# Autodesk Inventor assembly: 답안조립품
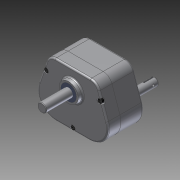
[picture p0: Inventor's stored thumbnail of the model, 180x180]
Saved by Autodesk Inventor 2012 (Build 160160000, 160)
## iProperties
Created: 2014-12
Part Number: 답안조립품
Document SubType Name: Assembly
Designer: Owner
Author: Owner
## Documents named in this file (14)
- C:\Documents and Settings\Owner\바탕 화면\441208V1002\답안조립품.iam
- C:\Documents and Settings\Owner\바탕 화면\441208V1002\1 본체.ipt
- C:\Documents and Settings\Owner\바탕 화면\441208V1002\커버.ipt
- C:\Documents and Settings\Owner\바탕 화면\441208V1002\M 5 x 35.ipt
- C:\Documents and Settings\Owner\바탕 화면\441208V1002\오일시일-D-15.ipt
- C:\Documents and Settings\Owner\바탕 화면\441208V1002\서브축.ipt
- C:\Documents and Settings\Owner\바탕 화면\441208V1002\베어링- 6203.ipt
- C:\Documents and Settings\Owner\바탕 화면\441208V1002\키5x5.ipt
- C:\Documents and Settings\Owner\바탕 화면\441208V1002\서브기어.ipt
- C:\Documents and Settings\Owner\바탕 화면\441208V1002\오일시일-D-17.ipt
- C:\Documents and Settings\Owner\바탕 화면\441208V1002\메인축.ipt
- C:\Documents and Settings\Owner\바탕 화면\441208V1002\메인기어.ipt
- C:\Documents and Settings\Owner\바탕 화면\441208V1002\멈춤링.ipt
- C:\Documents and Settings\Owner\바탕 화면\441208V1002\베어링- 6202.ipt
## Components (16 placed, 7 different names)
1. 1 본체:1
2. KS B 1003 - 미터 M 5 x 35:1 — 각도:1
3. KS B 1003 - 미터 M 5 x 35:2 — 각도:2
4. KS B 1003 - 미터 M 5 x 35:3 — 각도:3
5. KS B 2804 D D - 15 30 7:1
6. KS B 2804 D D - 15 30 7:2
7. KS B 2023 6203 - 17 x 40 x 12:1
8. KS B 2023 6203 - 17 x 40 x 12:2
9. KS B 2804 D D - 17 30 8:1
10. KS B 2023 6203 - 17 x 40 x 12:3
11. KS B 2023 6203 - 17 x 40 x 12:4
12. KS B 1336 17 x 1:1
13. KS B 1336 17 x 1:2
14. KS B 1336 17 x 1:3
15. KS B 2023 6202 - 15 x 35 x 11:1
16. KS B 2023 6202 - 15 x 35 x 11:2
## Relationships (3: Angle 3)
- 각도:1 [Angle]: KS B 1003 - 미터 M 5 x 35:1
- 각도:2 [Angle]: KS B 1003 - 미터 M 5 x 35:2
- 각도:3 [Angle]: KS B 1003 - 미터 M 5 x 35:3
